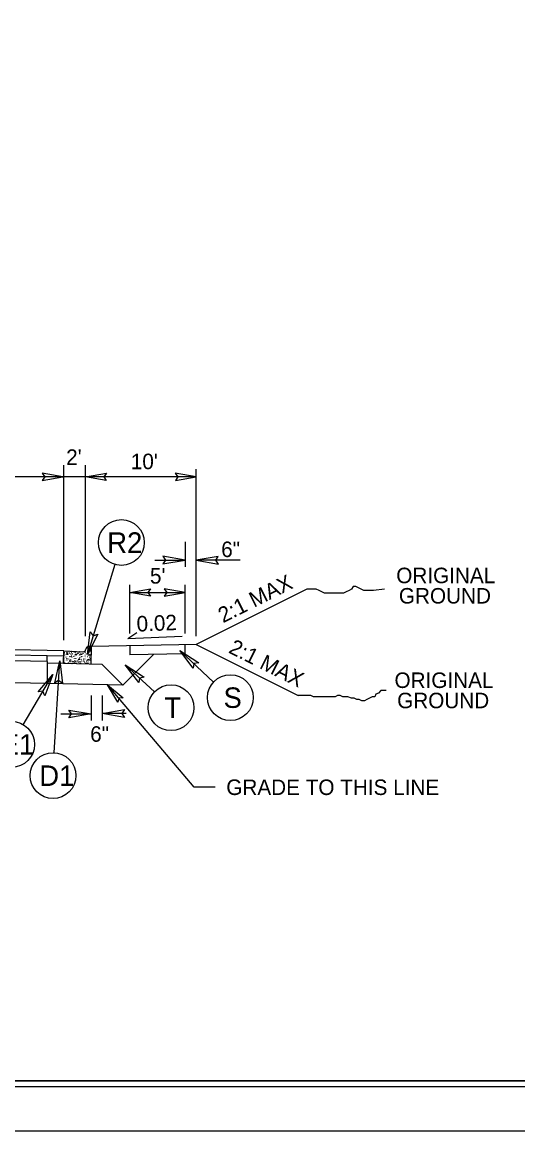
# Model space of a CAD drawing. Extents: x 1640342 to 1730599, y 538663 to 843747.
# Drawn here: x 1730051.2 to 1730096, y 539149.8 to 539249.9 of the extents above; entities that cross this region are included whole.
import ezdxf

# ---------------------------------------------------------------- set-up
doc = ezdxf.new("R2010")
doc.units = 0
for name, color, linetype in [('Default', 7, 'Continuous'), ('Prop Terminator CELL', 7, 'Continuous'), ('Sheet Clip Boundary CELL', 7, 'Continuous'), ('Sheet Layout Plan Border', 7, 'Continuous'), ('Sheet Plan CELL', 7, 'Continuous'), ('Sheet Plan Layout CELL', 7, 'Continuous'), ('Sheet Plot Border Inside CELL', 7, 'Continuous'), ('Sheet Plot Border Outside CELL', 7, 'Continuous'), ('Typical Curb CELL', 7, 'Continuous'), ('Typical Hinge Slope Arterial CELL', 7, 'Continuous'), ('Typical Hinge Slope Interstate CELL', 7, 'Continuous'), ('Typical ID Circle CELL', 7, 'Continuous'), ('Typical Pavement Slope CELL', 7, 'Continuous'), ('Typical Pavement Slope Information CELL', 7, 'Continuous'), ('Typical Shoulder Slope CELL', 7, 'Continuous'), ('Typical Terminator CELL', 7, 'Continuous'), ('Typical Text General CELL', 7, 'Continuous'), ('Typical Text ID Circle CELL', 7, 'Continuous')]:
    doc.layers.add(name, color=color, linetype=linetype)

msp = doc.modelspace()

# ---------------------------------------------------------------- linework, layer by layer
at = {"layer": 'Default'}
for p, q in [((1730054.98, 539194.14), (1730054.98, 539209.91)), ((1730054.98, 539194.1), (1730054.98, 539209.63)), ((1730056.95, 539194.46), (1730056.95, 539209.91)), ((1730054.91, 539208.87), (1730042.98, 539208.87)), ((1730056.91, 539208.87), (1730054.91, 539208.87)), ((1730066.95, 539208.87), (1730056.91, 539208.87)), ((1730066.95, 539194.46), (1730066.95, 539209.55)), ((1730065.95, 539202.99), (1730065.95, 539200.73)), ((1730063.2, 539201.35), (1730065.95, 539201.35)), ((1730070.92, 539201.33), (1730066.95, 539201.33)), ((1730060.95, 539194.71), (1730060.95, 539199.12)), ((1730065.95, 539194.71), (1730065.95, 539199.12)), ((1730060.95, 539198.42), (1730065.95, 539198.42)), ((1730057.45, 539189.12), (1730057.45, 539186.86)), ((1730058.45, 539189.12), (1730058.45, 539186.86)), ((1730054.72, 539187.46), (1730057.45, 539187.46)), ((1730060.62, 539187.48), (1730058.45, 539187.48))]:
    msp.add_line(p, q, dxfattribs=at)
for points in [[(1730053.04, 539208.54), (1730054.91, 539208.87), (1730053.03, 539209.2), (1730053.27, 539208.87)], [(1730058.82, 539208.54), (1730056.95, 539208.87), (1730058.83, 539209.2), (1730058.59, 539208.87)], [(1730065.07, 539208.54), (1730066.95, 539208.87), (1730065.06, 539209.2), (1730065.3, 539208.87)], [(1730062.82, 539198.1), (1730060.95, 539198.42), (1730062.83, 539198.75), (1730062.59, 539198.42)], [(1730064.07, 539198.1), (1730065.95, 539198.42), (1730064.06, 539198.75), (1730064.3, 539198.42)]]:
    msp.add_lwpolyline(points, close=True, dxfattribs=at)
at = {"layer": 'Prop Terminator CELL'}
msp.add_lwpolyline([(1730059.86, 539188.5), (1730058.93, 539190.08), (1730060.34, 539188.9), (1730059.95, 539188.87)], close=True, dxfattribs=at)
at = {"layer": 'Sheet Clip Boundary CELL'}
msp.add_lwpolyline([(1729883.99, 539154.28), (1730163.99, 539154.28), (1730163.99, 539321.98), (1730126.14, 539321.98), (1730126.14, 539364.28), (1729883.99, 539364.28)], close=True, dxfattribs=at)
at = {"layer": 'Sheet Layout Plan Border'}
msp.add_lwpolyline([(1729883.99, 539154.28), (1730163.99, 539154.28), (1730163.99, 539321.98), (1730126.14, 539321.98), (1730126.14, 539364.28), (1729883.99, 539364.28)], close=True, dxfattribs=at)
at = {"layer": 'Sheet Plan CELL'}
for points in [[(1730174, 539364.28), (1729873.99, 539364.28), (1729873.99, 539154.28), (1730173.99, 539154.28)], [(1729873.99, 539154.28), (1729873.99, 539364.27), (1730133.98, 539364.28), (1730133.99, 539334.27), (1730173.99, 539334.27), (1730173.99, 539154.28)]]:
    msp.add_lwpolyline(points, close=True, dxfattribs=at)
at = {"layer": 'Sheet Plan Layout CELL'}
msp.add_lwpolyline([(1729873.99, 539364.27), (1729873.99, 539154.28), (1730173.99, 539154.28), (1730173.99, 539321.98), (1730126.14, 539321.98), (1730126.14, 539364.28)], close=True, dxfattribs=at)
at = {"layer": 'Sheet Plot Border Inside CELL'}
msp.add_lwpolyline([(1729843.29, 539153.78), (1730176.49, 539153.78), (1730176.49, 539364.78), (1729843.29, 539364.78)], close=True, dxfattribs=at)
at = {"layer": 'Sheet Plot Border Outside CELL'}
msp.add_lwpolyline([(1729840.69, 539149.78), (1730177.39, 539149.78), (1730177.39, 539368.78), (1729840.69, 539368.78)], close=True, dxfattribs=at)
at = {"layer": 'Typical Curb CELL'}
for p, q in [((1730054.96, 539191.99), (1730054.98, 539193.16)), ((1730054.98, 539193.16), (1730056.72, 539193.06)), ((1730055.23, 539192.81), (1730055.32, 539192.93)), ((1730055.35, 539192.81), (1730055.23, 539192.81)), ((1730055.32, 539192.93), (1730055.35, 539192.81)), ((1730055.99, 539192.75), (1730056.06, 539192.86)), ((1730056.16, 539192.78), (1730055.99, 539192.75)), ((1730056.06, 539192.86), (1730056.16, 539192.78)), ((1730056.48, 539192.79), (1730056.57, 539192.91)), ((1730056.6, 539192.8), (1730056.48, 539192.79)), ((1730056.57, 539192.91), (1730056.6, 539192.8)), ((1730056.98, 539193.29), (1730056.98, 539193.3)), ((1730057.48, 539193.54), (1730057.22, 539193.54)), ((1730057.24, 539192.73), (1730057.31, 539192.84)), ((1730057.41, 539192.76), (1730057.24, 539192.73)), ((1730057.28, 539193.21), (1730057.3, 539193.11)), ((1730057.44, 539193.16), (1730057.28, 539193.21)), ((1730057.3, 539193.11), (1730057.44, 539193.16)), ((1730057.31, 539192.84), (1730057.41, 539192.76)), ((1730057.45, 539191.94), (1730057.48, 539193.54)), ((1730055.5, 539192.17), (1730055.56, 539192.28)), ((1730055.66, 539192.2), (1730055.5, 539192.17)), ((1730055.56, 539192.28), (1730055.66, 539192.2)), ((1730056.3, 539192.33), (1730056.37, 539192.45)), ((1730056.47, 539192.37), (1730056.3, 539192.33)), ((1730056.37, 539192.45), (1730056.47, 539192.37)), ((1730057.11, 539192.28), (1730057.17, 539192.39)), ((1730057.28, 539192.32), (1730057.11, 539192.28)), ((1730057.17, 539192.39), (1730057.28, 539192.32))]:
    msp.add_line(p, q, dxfattribs=at)
for centre in [(1730054.98, 539192.6), (1730054.99, 539192.91), (1730055.01, 539193.01), (1730055.04, 539192.77), (1730055.06, 539192.97), (1730055.14, 539192.81), (1730055.17, 539193.1), (1730055.19, 539192.58), (1730055.27, 539193.01), (1730055.32, 539193.11), (1730055.35, 539192.64), (1730055.46, 539193.05), (1730055.49, 539192.94), (1730055.55, 539192.62), (1730055.64, 539192.86), (1730055.67, 539193.03), (1730055.67, 539192.7), (1730055.69, 539193.08), (1730055.72, 539192.59), (1730055.76, 539192.88), (1730055.9, 539192.65), (1730055.94, 539193.04), (1730056.06, 539192.99), (1730056.07, 539192.6), (1730056.23, 539192.58), (1730056.24, 539192.89), (1730056.25, 539192.99), (1730056.29, 539192.75), (1730056.31, 539192.95), (1730056.39, 539192.79), (1730056.42, 539193.05), (1730056.44, 539192.56), (1730056.52, 539192.99), (1730056.6, 539192.62), (1730056.71, 539193.03), (1730056.74, 539192.92), (1730056.8, 539192.6), (1730056.88, 539192.84), (1730056.92, 539193.01), (1730056.92, 539192.68), (1730056.93, 539193.06), (1730056.97, 539192.57), (1730057.01, 539192.86), (1730057.15, 539192.63), (1730057.19, 539193.02), (1730057.25, 539193.46), (1730057.31, 539192.97), (1730057.32, 539192.58), (1730057.41, 539193.24), (1730057.46, 539193.43), (1730055.06, 539192.04), (1730055.08, 539192.48), (1730055.14, 539192.27), (1730055.17, 539192.12), (1730055.23, 539192.01), (1730055.25, 539192.44), (1730055.27, 539192.3), (1730055.41, 539192.07), (1730055.41, 539192.41), (1730055.58, 539192.02), (1730055.59, 539192.38), (1730055.73, 539192), (1730055.74, 539192.31), (1730055.79, 539192.17), (1730055.86, 539192.2), (1730055.93, 539192.08), (1730055.95, 539192.44), (1730055.98, 539192.29), (1730056.03, 539192.17), (1730056.07, 539192.47), (1730056.1, 539192.05), (1730056.21, 539192.23), (1730056.31, 539192.08), (1730056.38, 539192.19), (1730056.48, 539192.05), (1730056.53, 539192.17), (1730056.55, 539192.48), (1730056.6, 539192.34), (1730056.67, 539192.15), (1730056.75, 539192.39), (1730056.78, 539192.23), (1730056.84, 539192.12), (1730056.88, 539192.41), (1730056.97, 539192.05), (1730057.02, 539192.18), (1730057.14, 539192.02), (1730057.19, 539192.14), (1730057.34, 539192.12), (1730057.35, 539192.42), (1730057.41, 539192.28)]:
    msp.add_circle(centre, 0.00801, dxfattribs=at)
for centre, start, end in [((1730056.74, 539193.3), 266.7341, 359.1186), ((1730057.22, 539193.3), 89.1186, 179.1186)]:
    msp.add_arc(centre, 0.239, start, end, dxfattribs=at)
at = {"layer": 'Typical Hinge Slope Arterial CELL'}
for p, q in [((1730076.94, 539198.72), (1730066.95, 539193.72)), ((1730066.95, 539193.72), (1730076.16, 539189.1))]:
    msp.add_line(p, q, dxfattribs=at)
msp.add_lwpolyline([(1730083.96, 539198.72), (1730082.97, 539198.6), (1730082.73, 539198.6), (1730082.36, 539198.6), (1730082.11, 539198.6), (1730081.86, 539198.72), (1730081.62, 539198.84), (1730081.37, 539198.97), (1730081.13, 539198.97), (1730081, 539198.72), (1730080.76, 539198.6), (1730080.51, 539198.47), (1730080.26, 539198.35), (1730080.02, 539198.35), (1730079.77, 539198.35), (1730079.53, 539198.35), (1730079.28, 539198.35), (1730079.03, 539198.35), (1730078.79, 539198.35), (1730078.54, 539198.35), (1730078.29, 539198.47), (1730078.05, 539198.6), (1730077.8, 539198.72), (1730077.43, 539198.72), (1730077.19, 539198.72), (1730076.94, 539198.72)], dxfattribs=at)
at = {"layer": 'Typical Hinge Slope Interstate CELL'}
msp.add_lwpolyline([(1730084.11, 539189.56), (1730083.88, 539189.56), (1730083.65, 539189.56), (1730083.42, 539189.33), (1730083.19, 539189.22), (1730083.08, 539188.99), (1730082.84, 539188.99), (1730082.61, 539188.87), (1730082.38, 539188.76), (1730082.15, 539188.64), (1730081.92, 539188.64), (1730081.69, 539188.76), (1730081.46, 539188.76), (1730081.23, 539188.87), (1730081, 539188.87), (1730080.66, 539188.99), (1730080.43, 539188.99), (1730080.2, 539188.99), (1730079.97, 539189.1), (1730079.73, 539189.1), (1730079.5, 539188.99), (1730079.27, 539188.99), (1730079.04, 539188.99), (1730078.81, 539188.99), (1730078.58, 539188.99), (1730078.24, 539188.99), (1730077.89, 539188.99), (1730077.55, 539188.99), (1730077.32, 539189.1), (1730076.97, 539189.1), (1730076.62, 539189.1), (1730076.16, 539189.1)], dxfattribs=at)
at = {"layer": 'Typical ID Circle CELL'}
for p, q in [((1730059.59, 539200.94), (1730057.13, 539192.82)), ((1730068.52, 539190.33), (1730065.46, 539193.19)), ((1730054.12, 539183.94), (1730054.62, 539192.24)), ((1730063.17, 539189.43), (1730060.53, 539191.89)), ((1730051.32, 539186.47), (1730053.99, 539191.01))]:
    msp.add_line(p, q, dxfattribs=at)
for centre in [(1730060.19, 539202.93), (1730070.04, 539188.92), (1730064.68, 539188.01), (1730050.27, 539184.69), (1730054.01, 539181.87)]:
    msp.add_circle(centre, 2.07, dxfattribs=at)
at = {"layer": 'Typical Pavement Slope CELL'}
for p, q in [((1730054.98, 539193.16), (1730020.91, 539193.84)), ((1730053.48, 539192.19), (1730020.9, 539192.84)), ((1730054.98, 539192.66), (1730020.91, 539193.34)), ((1730053.48, 539192.19), (1730053.48, 539192.69)), ((1730054.96, 539193.16), (1730054.96, 539191.99)), ((1730063.09, 539192.81), (1730060.33, 539190.05)), ((1730054.98, 539191.99), (1730053.48, 539192.02)), ((1730058.45, 539191.92), (1730054.96, 539191.99)), ((1730058.45, 539191.92), (1730060.33, 539190.05)), ((1730053.48, 539190.19), (1730020.91, 539190.84)), ((1730060.33, 539190.05), (1730053.53, 539190.19))]:
    msp.add_line(p, q, dxfattribs=at)
msp.add_lwpolyline([(1730053.48, 539192.19), (1730053.48, 539190.16)], dxfattribs=at)
at = {"layer": 'Typical Pavement Slope Information CELL'}
for q in [(1730061.6, 539194.79), (1730065.68, 539194.47)]:
    msp.add_line((1730060.78, 539194.27), q, dxfattribs=at)
at = {"layer": 'Typical Shoulder Slope CELL'}
for p, q in [((1730066.95, 539193.72), (1730057.48, 539193.54)), ((1730060.95, 539193.61), (1730060.95, 539192.77)), ((1730065.95, 539192.87), (1730065.95, 539193.71)), ((1730065.95, 539192.87), (1730060.95, 539192.77))]:
    msp.add_line(p, q, dxfattribs=at)
at = {"layer": 'Typical Terminator CELL'}
for p, q in [((1730066.76, 539180.82), (1730058.93, 539190.08)), ((1730068.67, 539180.82), (1730066.76, 539180.82))]:
    msp.add_line(p, q, dxfattribs=at)
for points in [[(1730063.94, 539201.01), (1730065.95, 539201.35), (1730063.93, 539201.71), (1730064.18, 539201.35)], [(1730068.95, 539201.68), (1730066.95, 539201.33), (1730068.97, 539200.97), (1730068.71, 539201.33)], [(1730058.05, 539194.64), (1730057.13, 539192.82), (1730057.38, 539194.85), (1730057.64, 539194.51)], [(1730066.69, 539191.57), (1730065.46, 539193.19), (1730067.18, 539192.07), (1730066.75, 539191.99)], [(1730054.16, 539190.26), (1730054.62, 539192.24), (1730054.86, 539190.2), (1730054.52, 539190.48)], [(1730061.76, 539190.27), (1730060.53, 539191.89), (1730062.25, 539190.77), (1730061.82, 539190.69)], [(1730052.67, 539189.45), (1730053.99, 539191.01), (1730053.27, 539189.09), (1730053.1, 539189.49)], [(1730055.45, 539187.8), (1730057.45, 539187.46), (1730055.44, 539187.1), (1730055.69, 539187.46)], [(1730060.46, 539187.13), (1730058.45, 539187.48), (1730060.47, 539187.84), (1730060.22, 539187.48)]]:
    msp.add_lwpolyline(points, close=True, dxfattribs=at)

# ---------------------------------------------------------------- texts
at = {"layer": 'Default'}
for s, p in [("10'", (1730061.04, 539209.56)), ("5'", (1730062.77, 539199.22)), ('ORIGINAL', (1730085.03, 539199.26)), ('GROUND', (1730085.27, 539197.42)), ('ORIGINAL', (1730084.87, 539189.79)), ('GROUND', (1730085.11, 539187.96)), ('6"', (1730057.37, 539184.93))]:
    msp.add_text(s, height=1.4, dxfattribs=at).set_placement(p)
msp.add_text('6"', height=1.4, rotation=360, dxfattribs=at).set_placement((1730069.21, 539201.62))
at = {"layer": 'Typical Hinge Slope Interstate CELL'}
for rotation, p in [(26.5646, (1730069.38, 539195.63)), (333.4354, (1730069.79, 539193.01))]:
    msp.add_text('2:1 MAX', height=1.4, rotation=rotation, dxfattribs=at).set_placement(p)
at = {"layer": 'Typical Pavement Slope Information CELL'}
msp.add_text("2'", height=1.4, dxfattribs=at).set_placement((1730055.2, 539209.95))
msp.add_text('0.02', height=1.4, rotation=2.3003, dxfattribs=at).set_placement((1730061.59, 539194.88))
at = {"layer": 'Typical Text General CELL'}
msp.add_text('GRADE TO THIS LINE', height=1.4, rotation=360, dxfattribs=at).set_placement((1730069.67, 539180.12))
at = {"layer": 'Typical Text ID Circle CELL'}
for s, height, p in [('R2', 1.854, (1730058.91, 539202)), ('S', 1.85, (1730069.42, 539187.99)), ('T', 1.85, (1730064.07, 539187.09)), ('E1', 1.854, (1730049.28, 539183.76)), ('D1', 1.854, (1730052.77, 539180.94))]:
    msp.add_text(s, height=height, dxfattribs=at).set_placement(p)

doc.saveas('drawing.dxf')
